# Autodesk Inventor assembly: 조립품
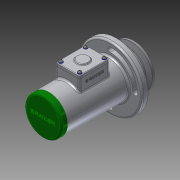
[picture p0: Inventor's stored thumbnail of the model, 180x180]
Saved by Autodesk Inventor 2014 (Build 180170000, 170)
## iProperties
Created: 2017-05
Part Number: 조립품
Document SubType Name: Assembly
Designer: oa51
Author: oa51
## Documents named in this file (20)
- C:\Users\oa51\Desktop\470508V1016\조립품.iam
- C:\Users\oa51\Desktop\470508V1016\본체.ipt
- C:\Users\oa51\Desktop\470508V1016\사이드 커버.ipt
- 사이드 커버.ipt
- C:\Users\oa51\Desktop\470508V1016\베어링 15 x 35 x 11.ipt
- C:\Users\oa51\Desktop\470508V1016\축.ipt
- C:\Users\oa51\Desktop\470508V1016\멈춤링 35x1.6.ipt
- C:\Users\oa51\Desktop\470508V1016\멈춤링 15 x 1.ipt
- C:\Users\oa51\Desktop\470508V1016\오일 실 15 25 7.ipt
- C:\Users\oa51\Desktop\470508V1016\부시1.ipt
- C:\Users\oa51\Desktop\470508V1016\부시2.ipt
- C:\Users\oa51\Desktop\470508V1016\와셔 10x21.ipt
- C:\Users\oa51\Desktop\470508V1016\너트 M10.ipt
- C:\Users\oa51\Desktop\470508V1016\키 4 x 4 x 18.ipt
- C:\Users\oa51\Desktop\470508V1016\V-벨트풀리.ipt
- C:\Users\oa51\Desktop\470508V1016\와셔 4x16.ipt
- C:\Users\oa51\Desktop\470508V1016\볼트 M4 x 10.ipt
- C:\Users\oa51\Desktop\470508V1016\탑 커버.ipt
- C:\Users\oa51\Desktop\470508V1016\와셔 3x6.ipt
- C:\Users\oa51\Desktop\470508V1016\십자볼트 M3 x 10.ipt
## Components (2 placed, 2 different names)
1. V-벨트풀리:1 — 각도:4
2. ISO 4017 M4 x 10:1 — 각도:5
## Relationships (2: Angle 2)
- 각도:4 [Angle]: V-벨트풀리:1
- 각도:5 [Angle]: ISO 4017 M4 x 10:1
